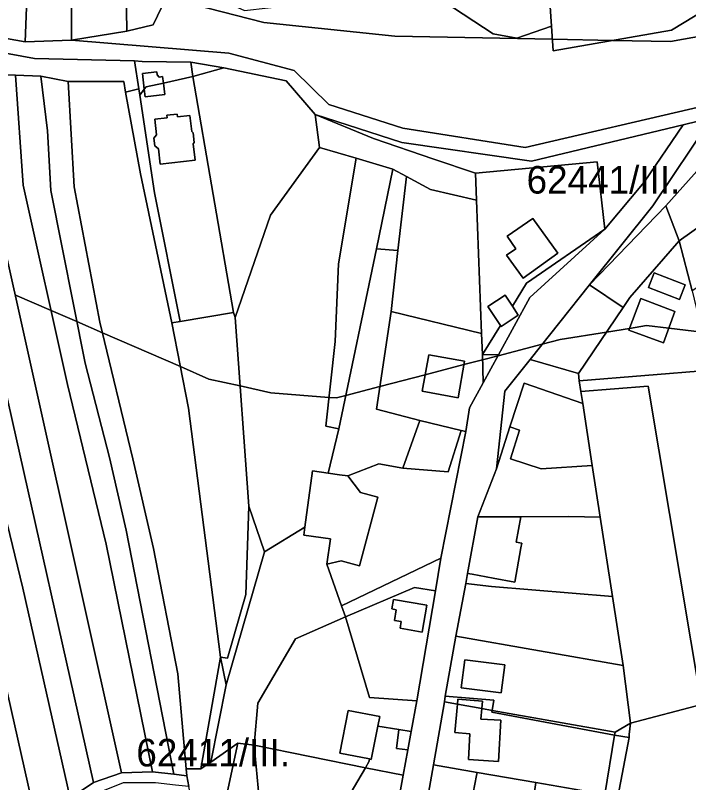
# Model space of a CAD drawing. Extents: x -502026 to -497664, y -1143484 to -1138019.
# Drawn here: x -499368.7 to -499173.2, y -1141026.2 to -1140803.4 of the extents above; entities that cross this region are included whole.
import ezdxf

# ---------------------------------------------------------------- set-up
doc = ezdxf.new("R2010")
doc.units = 0
for name, color, linetype in [('25', 7, 'Continuous'), ('37', 7, 'Continuous'), ('43', 7, 'Continuous'), ('49', 7, 'Continuous'), ('55', 7, 'Continuous'), ('62', 7, 'Continuous'), ('7', 7, 'Continuous')]:
    doc.layers.add(name, color=color, linetype=linetype)

msp = doc.modelspace()

# ---------------------------------------------------------------- linework, layer by layer
at = {"layer": '25'}
for points in [[(-499197.54, -1140865.53), (-499220.31, -1140881.21), (-499224.42, -1140887.86), (-499226.54, -1140884.64), (-499231.53, -1140887.94), (-499227.88, -1140893.47), (-499233.09, -1140901.89), (-499233.33, -1140895.75), (-499234.85, -1140857.1), (-499235.11, -1140849.28), (-499199.75, -1140845.95)], [(-499211.18, -1140872.5), (-499218.51, -1140862.37), (-499225.92, -1140867.49), (-499223.41, -1140871.18), (-499226.08, -1140873), (-499221.25, -1140879.73)], [(-499172.2, -1140883.42), (-499168.7, -1140897.93), (-499166.92, -1140906.4), (-499204.99, -1140909.49), (-499205.25, -1140907.4), (-499192.25, -1140888.2), (-499190.28, -1140885.29), (-499175.96, -1140868.88)], [(-499174.29, -1140881.66), (-499183.26, -1140878.2), (-499184.91, -1140882.42), (-499175.92, -1140885.89)], [(-499177.24, -1140889.37), (-499187.16, -1140885.61), (-499190.64, -1140894.79), (-499180.52, -1140898.45)], [(-499304.87, -1140891.11), (-499300.88, -1140945.93), (-499301.8, -1140971.52), (-499307.12, -1140990.05), (-499309.15, -1140989.78), (-499318.38, -1140917.5), (-499323.23, -1140892.73), (-499320.84, -1140892.29), (-499305.38, -1140889.66)], [(-499233.33, -1140895.75), (-499233.09, -1140901.89), (-499232.84, -1140910.06), (-499236.82, -1140917.34), (-499237.88, -1140924.28), (-499239.24, -1140923.94), (-499251.3, -1140921.01), (-499263.86, -1140917.78), (-499259.57, -1140889.43)], [(-499238.33, -1140903.78), (-499248.65, -1140901.96), (-499250.57, -1140912.55), (-499240.17, -1140914.47)], [(-499149.96, -1140998.01), (-499169.47, -1141003.49), (-499185.03, -1140911.08), (-499204.51, -1140912.61), (-499204.99, -1140909.49), (-499166.92, -1140906.4), (-499166.32, -1140909.62)], [(-499169.47, -1141003.49), (-499190.13, -1141008.87), (-499192.27, -1140992.2), (-499195.38, -1140972.18), (-499198.96, -1140949.07), (-499201.24, -1140934.07), (-499203.98, -1140916.08), (-499204.51, -1140912.61), (-499185.03, -1140911.08)], [(-499239.24, -1140923.94), (-499243.03, -1140935.97), (-499256.25, -1140934.9), (-499251.3, -1140921.01)], [(-499237.88, -1140924.28), (-499245.16, -1140961.04), (-499274.05, -1140974.83), (-499278.24, -1140962.75), (-499274.1, -1140961.77), (-499268.82, -1140963.21), (-499263.44, -1140943.34), (-499268.48, -1140941.98), (-499272.21, -1140937.1), (-499263.21, -1140933.63), (-499256.25, -1140934.9), (-499243.03, -1140935.97), (-499239.24, -1140923.94)], [(-499201.24, -1140934.07), (-499198.96, -1140949.07), (-499207.98, -1140948.89), (-499221.95, -1140948.97), (-499234.39, -1140949.05), (-499229.06, -1140935.09), (-499225.13, -1140922.92), (-499222.32, -1140923.81), (-499224.98, -1140932.15), (-499216.06, -1140935.06)], [(-499198.96, -1140949.07), (-499195.38, -1140972.18), (-499230.44, -1140969.23), (-499237.96, -1140968.39), (-499237.4, -1140965.44), (-499236.07, -1140965.69), (-499230, -1140966.78), (-499223.72, -1140967.95), (-499221.96, -1140958.01), (-499221.67, -1140956.64), (-499223.31, -1140956.33), (-499221.95, -1140948.97), (-499207.98, -1140948.89)], [(-499278.24, -1140962.75), (-499274.05, -1140974.83), (-499272.81, -1140978.04), (-499287.31, -1140984.39), (-499298.29, -1141003.14), (-499299.38, -1141015.27), (-499304.05, -1141014.72), (-499311.97, -1141020.25), (-499307.52, -1140997.79), (-499296.35, -1140959.15), (-499284.66, -1140951.98), (-499284.98, -1140954.32), (-499277.15, -1140955.39)], [(-499195.38, -1140972.18), (-499192.27, -1140992.2), (-499240.81, -1140983.63), (-499237.96, -1140968.39), (-499230.44, -1140969.23)], [(-499246.75, -1140970.51), (-499252.11, -1141002.41), (-499265.85, -1141001.45), (-499272.81, -1140978.04), (-499252.78, -1140969.56)], [(-499249.2, -1140974.61), (-499258.96, -1140972.98), (-499259.42, -1140975.76), (-499258.11, -1140975.98), (-499258.62, -1140979.06), (-499256.67, -1140979.38), (-499257, -1140981.35), (-499250.62, -1140982.5)], [(-499252.11, -1141002.41), (-499253.8, -1141011.37), (-499257.38, -1141010.76), (-499263.46, -1141009.82), (-499262.91, -1141007.02), (-499272.06, -1141005.24), (-499274.5, -1141017.6), (-499265.89, -1141019.3), (-499265.96, -1141019.96), (-499267.06, -1141021.83), (-499299.38, -1141015.27), (-499298.29, -1141003.14), (-499287.31, -1140984.39), (-499272.81, -1140978.04), (-499265.85, -1141001.45)], [(-499192.27, -1140992.2), (-499190.13, -1141008.87), (-499194.56, -1141011.49), (-499230.28, -1141005.19), (-499229.81, -1141002.27), (-499243.87, -1141001.08), (-499240.81, -1140983.63)], [(-499226.6, -1140991.99), (-499238.2, -1140990.48), (-499239.26, -1140998.61), (-499227.66, -1141000.12)], [(-499230.28, -1141005.19), (-499233.26, -1141004.68), (-499233.04, -1141002.55), (-499240.26, -1141001.93), (-499240.38, -1141003.42), (-499244.15, -1141002.76), (-499243.87, -1141001.08), (-499229.81, -1141002.27)], [(-499240.38, -1141003.42), (-499241.07, -1141011.66), (-499236.71, -1141011.96), (-499237.13, -1141019.48), (-499228.43, -1141020.02), (-499227.73, -1141008.05), (-499233.56, -1141007.73), (-499233.26, -1141004.68), (-499230.28, -1141005.19), (-499230.36, -1141005.73), (-499194.72, -1141012.36), (-499197.6, -1141029.59), (-499217.58, -1141026.14), (-499234.64, -1141023.19), (-499247.31, -1141021), (-499244.15, -1141002.76)], [(-499194.56, -1141011.49), (-499194.72, -1141012.36), (-499230.36, -1141005.73), (-499230.28, -1141005.19)], [(-499299.38, -1141015.27), (-499297.29, -1141036.96), (-499298.32, -1141041.92), (-499309.49, -1141040), (-499304.05, -1141014.72)], [(-499267.06, -1141021.83), (-499272.46, -1141031.03), (-499275.72, -1141040.45), (-499277.52, -1141045.65), (-499281.4, -1141044.73), (-499298.32, -1141041.92), (-499297.29, -1141036.96), (-499299.38, -1141015.27)], [(-499234.64, -1141023.19), (-499234.82, -1141024.1), (-499235.82, -1141029.13), (-499237.29, -1141028.84), (-499237.66, -1141030.69), (-499236.19, -1141030.98), (-499237.06, -1141035.33), (-499229.07, -1141036.96), (-499227.41, -1141037.3), (-499227.95, -1141041), (-499222.45, -1141041.81), (-499222.37, -1141041.27), (-499219.87, -1141041.64), (-499219.24, -1141037.37), (-499217.58, -1141026.14), (-499197.6, -1141029.59), (-499199.94, -1141043.6), (-499205.07, -1141047.08), (-499250.48, -1141039.11), (-499247.31, -1141021)]]:
    msp.add_lwpolyline(points, close=True, dxfattribs=at)
at = {"layer": '37'}
for points in [[(-499093.69, -1140800.62), (-499104.95, -1140814.88), (-499109.51, -1140803.7), (-499127.89, -1140814.52), (-499149.4, -1140825.3), (-499162.04, -1140835.16), (-499163.96, -1140837.47), (-499165.34, -1140840.32), (-499168.31, -1140844.22), (-499168.31, -1140845.8), (-499179.89, -1140858.73), (-499202.02, -1140881.64), (-499183.66, -1140858.73), (-499166.49, -1140833.21), (-499109.48, -1140803.35), (-499095.98, -1140796.53)], [(-499305.38, -1140889.66), (-499320.84, -1140892.29), (-499328.27, -1140854.9), (-499332.57, -1140826.63), (-499331.24, -1140824.89), (-499330.99, -1140827.12), (-499325.29, -1140826.38), (-499325.71, -1140823.08), (-499317.16, -1140821.14)], [(-499158.93, -1140856.74), (-499175.96, -1140868.88), (-499179.89, -1140858.73), (-499168.31, -1140845.8), (-499168.31, -1140844.22), (-499165.34, -1140840.32), (-499163.96, -1140837.47), (-499162.04, -1140835.16), (-499149.4, -1140825.3), (-499165.76, -1140843.54)], [(-499321.7, -1140832.11), (-499324.66, -1140832.44), (-499324.57, -1140833.15), (-499328.14, -1140833.59), (-499327.66, -1140838.07), (-499328.45, -1140839.09), (-499328.18, -1140841.33), (-499327.15, -1140842.16), (-499326.61, -1140846.63), (-499316.5, -1140845.46), (-499317.05, -1140840.74), (-499316.74, -1140840.29), (-499317.06, -1140837.57), (-499317.46, -1140837.14), (-499318.01, -1140832.46), (-499321.63, -1140832.86)], [(-499269.76, -1140844.9), (-499274.85, -1140875.52), (-499275.85, -1140898.11), (-499278.57, -1140922.64), (-499274.78, -1140923.45), (-499277.84, -1140936.32), (-499282.42, -1140935.7), (-499284.66, -1140951.98), (-499296.35, -1140959.15), (-499300.88, -1140945.93), (-499304.87, -1140891.11), (-499294.61, -1140861.42), (-499280.38, -1140841.77)], [(-499172.2, -1140883.42), (-499175.96, -1140868.88), (-499158.93, -1140856.74), (-499141.03, -1140844.02), (-499134.24, -1140858.85)], [(-499259.06, -1140848.12), (-499263.87, -1140871.19), (-499274.78, -1140923.45), (-499278.57, -1140922.64), (-499275.85, -1140898.11), (-499274.85, -1140875.52), (-499269.76, -1140844.9)], [(-499255.12, -1140850.19), (-499257.68, -1140871.65), (-499263.87, -1140871.19), (-499259.06, -1140848.12)], [(-499234.85, -1140857.1), (-499233.33, -1140895.75), (-499259.57, -1140889.43), (-499257.68, -1140871.65), (-499255.12, -1140850.19), (-499248.22, -1140854)], [(-499175.96, -1140868.88), (-499190.28, -1140885.29), (-499192.25, -1140888.2), (-499202.02, -1140881.64), (-499179.89, -1140858.73)], [(-499257.68, -1140871.65), (-499259.57, -1140889.43), (-499263.86, -1140917.78), (-499251.3, -1140921.01), (-499256.25, -1140934.9), (-499263.21, -1140933.63), (-499272.21, -1140937.1), (-499274.6, -1140936.77), (-499277.84, -1140936.32), (-499274.78, -1140923.45), (-499263.87, -1140871.19)], [(-499192.25, -1140888.2), (-499205.25, -1140907.4), (-499219.29, -1140903.33), (-499202.02, -1140881.64)], [(-499205.25, -1140907.4), (-499204.99, -1140909.49), (-499204.51, -1140912.61), (-499203.98, -1140916.08), (-499221.01, -1140910.17), (-499225.13, -1140922.92), (-499229.06, -1140935.09), (-499226.63, -1140912.54), (-499219.29, -1140903.33)], [(-499296.35, -1140959.15), (-499307.52, -1140997.79), (-499309.15, -1140989.78), (-499307.12, -1140990.05), (-499301.8, -1140971.52), (-499300.88, -1140945.93)], [(-499307.52, -1140997.79), (-499311.97, -1141020.25), (-499314.88, -1141022.19), (-499309.15, -1140989.78)], [(-499167.34, -1141225.18), (-499190.36, -1141233.78), (-499185.74, -1141195.87), (-499181.22, -1141101.09), (-499185.55, -1141045.62), (-499196.67, -1141045.66), (-499193.78, -1141030.25), (-499190.54, -1141013.08), (-499190.51, -1141012.2), (-499190.13, -1141008.87), (-499169.47, -1141003.49), (-499161.86, -1141074.87), (-499164.09, -1141140.88)], [(-499253.8, -1141011.37), (-499254.75, -1141016.63), (-499258.07, -1141016.22), (-499257.38, -1141010.76)]]:
    msp.add_lwpolyline(points, close=True, dxfattribs=at)
at = {"layer": '43'}
msp.add_lwpolyline([(-499098.45, -1140792.47), (-499169.08, -1140829.79), (-499220.72, -1140841.83), (-499256.21, -1140836.16), (-499277.72, -1140829.32), (-499287.7, -1140819.38), (-499306.66, -1140814.44), (-499352.42, -1140810.64), (-499336.3, -1140807.98), (-499328.65, -1140806.13), (-499324.82, -1140798.07), (-499318.22, -1140791.11), (-499315.45, -1140795.96), (-499302.12, -1140802.04), (-499267.8, -1140798.07), (-499244.32, -1140799.43), (-499230, -1140808.8), (-499223.13, -1140810.06), (-499213.06, -1140806.58), (-499212.54, -1140813.69), (-499178.21, -1140807.73), (-499161.8, -1140797.63), (-499134.65, -1140793.45), (-499107.41, -1140785.15)], close=True, dxfattribs=at)
at = {"layer": '49'}
for points in [[(-499213.58, -1140799.48), (-499213.06, -1140806.58), (-499223.13, -1140810.06), (-499230, -1140808.8), (-499244.32, -1140799.43)], [(-499161.8, -1140797.63), (-499178.21, -1140807.73), (-499212.54, -1140813.69), (-499213.06, -1140806.58), (-499213.58, -1140799.48)]]:
    msp.add_lwpolyline(points, dxfattribs=at)
at = {"layer": '55'}
for points in [[(-499411.74, -1140801.37), (-499390.44, -1140806.13), (-499384.16, -1140807.53), (-499376.79, -1140809.18), (-499365.81, -1140811.09), (-499352.42, -1140810.64), (-499306.66, -1140814.44), (-499287.7, -1140819.38), (-499277.72, -1140829.32), (-499256.21, -1140836.16), (-499220.72, -1140841.83), (-499169.08, -1140829.79), (-499098.45, -1140792.47)], [(-499109.48, -1140803.35), (-499166.49, -1140833.21), (-499174.8, -1140835.2), (-499218.89, -1140845.72), (-499256.52, -1140840.37), (-499281.61, -1140832.2), (-499290.1, -1140822.45), (-499308.12, -1140818.62), (-499317.73, -1140817), (-499331.83, -1140816.86), (-499334.13, -1140816.64), (-499363.08, -1140815.92), (-499412.53, -1140806.88), (-499433.39, -1140809.57), (-499443.61, -1140810.8), (-499451.13, -1140803.54), (-499477.19, -1140803.19), (-499501.07, -1140809.22), (-499520.46, -1140808.75), (-499530.45, -1140804.22), (-499532.5, -1140804.46), (-499550.63, -1140806.59)], [(-499258.3, -1141036.16), (-499256.1, -1141024.05), (-499254.75, -1141016.63), (-499253.8, -1141011.37), (-499252.11, -1141002.41), (-499246.75, -1140970.51), (-499245.16, -1140961.04), (-499237.88, -1140924.28), (-499236.82, -1140917.34), (-499232.84, -1140910.06), (-499228.39, -1140901.93), (-499219.31, -1140885.35), (-499197.54, -1140865.53), (-499186.16, -1140851.8), (-499174.8, -1140835.2), (-499166.49, -1140833.21), (-499183.66, -1140858.73), (-499202.02, -1140881.64), (-499219.29, -1140903.33), (-499226.63, -1140912.54), (-499229.06, -1140935.09), (-499234.39, -1140949.05), (-499237.4, -1140965.44), (-499237.96, -1140968.39), (-499240.81, -1140983.63), (-499243.87, -1141001.08), (-499244.15, -1141002.76), (-499247.31, -1141021), (-499250.48, -1141039.11)]]:
    msp.add_lwpolyline(points, dxfattribs=at)
for points in [[(-499334.13, -1140816.64), (-499332.86, -1140824.76), (-499336.66, -1140825.71), (-499337.23, -1140822.63), (-499353.36, -1140822.64), (-499361.27, -1140821.06), (-499368.62, -1140820.79), (-499378.44, -1140820.43), (-499389.02, -1140817.72), (-499400.07, -1140816.06), (-499411.8, -1140814.3), (-499423.03, -1140811.84), (-499433.39, -1140809.57), (-499412.53, -1140806.88), (-499363.08, -1140815.92)], [(-499317.73, -1140817), (-499317.16, -1140821.14), (-499325.71, -1140823.08), (-499325.96, -1140821.17), (-499326.97, -1140821.32), (-499327.5, -1140820.64), (-499327.63, -1140819.79), (-499331.74, -1140820.34), (-499331.24, -1140824.89), (-499332.57, -1140826.63), (-499332.86, -1140824.76), (-499334.13, -1140816.64), (-499331.83, -1140816.86)], [(-499308.12, -1140818.62), (-499317.16, -1140821.14), (-499317.73, -1140817)], [(-499325.71, -1140823.08), (-499330.71, -1140824.21), (-499331.24, -1140824.89), (-499331.74, -1140820.34), (-499327.63, -1140819.79), (-499327.5, -1140820.64), (-499326.97, -1140821.32), (-499325.96, -1140821.17)], [(-499331.24, -1140824.89), (-499330.71, -1140824.21), (-499325.71, -1140823.08), (-499325.29, -1140826.38), (-499330.99, -1140827.12)], [(-499332.57, -1140826.63), (-499328.27, -1140854.9), (-499320.84, -1140892.29), (-499323.23, -1140892.73), (-499332.37, -1140849.39), (-499336.66, -1140825.71), (-499332.86, -1140824.76)], [(-499321.7, -1140832.11), (-499321.63, -1140832.86), (-499318.01, -1140832.46), (-499317.46, -1140837.14), (-499317.06, -1140837.57), (-499316.74, -1140840.29), (-499317.05, -1140840.74), (-499316.5, -1140845.46), (-499326.61, -1140846.63), (-499327.15, -1140842.16), (-499328.18, -1140841.33), (-499328.45, -1140839.09), (-499327.66, -1140838.07), (-499328.14, -1140833.59), (-499324.57, -1140833.15), (-499324.66, -1140832.44)], [(-499235.11, -1140849.28), (-499234.85, -1140857.1), (-499248.22, -1140854), (-499255.12, -1140850.19), (-499259.06, -1140848.12), (-499269.76, -1140844.9), (-499280.38, -1140841.77), (-499281.61, -1140832.2), (-499264.76, -1140839.14), (-499247.22, -1140845.16)], [(-499174.8, -1140835.2), (-499186.16, -1140851.8), (-499197.54, -1140865.53), (-499199.75, -1140845.95), (-499235.11, -1140849.28), (-499247.22, -1140845.16), (-499264.76, -1140839.14), (-499281.61, -1140832.2), (-499256.52, -1140840.37), (-499218.89, -1140845.72)], [(-499211.18, -1140872.5), (-499221.25, -1140879.73), (-499226.08, -1140873), (-499223.41, -1140871.18), (-499225.92, -1140867.49), (-499218.51, -1140862.37)], [(-499228.39, -1140901.93), (-499233.09, -1140901.89), (-499227.88, -1140893.47), (-499227.67, -1140893.79), (-499222.69, -1140890.48), (-499224.42, -1140887.86), (-499220.31, -1140881.21), (-499197.54, -1140865.53), (-499219.31, -1140885.35)], [(-499174.29, -1140881.66), (-499175.92, -1140885.89), (-499184.91, -1140882.42), (-499183.26, -1140878.2)], [(-499224.42, -1140887.86), (-499222.69, -1140890.48), (-499227.67, -1140893.79), (-499227.88, -1140893.47), (-499231.53, -1140887.94), (-499226.54, -1140884.64)], [(-499177.24, -1140889.37), (-499180.52, -1140898.45), (-499190.64, -1140894.79), (-499187.16, -1140885.61)], [(-499238.33, -1140903.78), (-499240.17, -1140914.47), (-499250.57, -1140912.55), (-499248.65, -1140901.96)], [(-499228.39, -1140901.93), (-499232.84, -1140910.06), (-499233.09, -1140901.89)], [(-499203.98, -1140916.08), (-499201.24, -1140934.07), (-499216.06, -1140935.06), (-499224.98, -1140932.15), (-499222.32, -1140923.81), (-499225.13, -1140922.92), (-499221.01, -1140910.17)], [(-499277.84, -1140936.32), (-499274.6, -1140936.77), (-499272.21, -1140937.1), (-499268.48, -1140941.98), (-499263.44, -1140943.34), (-499268.82, -1140963.21), (-499274.1, -1140961.77), (-499278.24, -1140962.75), (-499277.15, -1140955.39), (-499284.98, -1140954.32), (-499284.66, -1140951.98), (-499282.42, -1140935.7)], [(-499237.4, -1140965.44), (-499234.39, -1140949.05), (-499221.95, -1140948.97), (-499223.31, -1140956.33), (-499221.67, -1140956.64), (-499221.96, -1140958.01), (-499223.72, -1140967.95), (-499230, -1140966.78), (-499236.07, -1140965.69)], [(-499246.75, -1140970.51), (-499252.78, -1140969.56), (-499272.81, -1140978.04), (-499274.05, -1140974.83), (-499245.16, -1140961.04)], [(-499249.2, -1140974.61), (-499250.62, -1140982.5), (-499257, -1140981.35), (-499256.67, -1140979.38), (-499258.62, -1140979.06), (-499258.11, -1140975.98), (-499259.42, -1140975.76), (-499258.96, -1140972.98)], [(-499226.6, -1140991.99), (-499227.66, -1141000.12), (-499239.26, -1140998.61), (-499238.2, -1140990.48)], [(-499233.26, -1141004.68), (-499240.38, -1141003.42), (-499240.26, -1141001.93), (-499233.04, -1141002.55)], [(-499233.26, -1141004.68), (-499233.56, -1141007.73), (-499227.73, -1141008.05), (-499228.43, -1141020.02), (-499237.13, -1141019.48), (-499236.71, -1141011.96), (-499241.07, -1141011.66), (-499240.38, -1141003.42)], [(-499263.46, -1141009.82), (-499265.35, -1141019.41), (-499265.89, -1141019.3), (-499274.5, -1141017.6), (-499272.06, -1141005.24), (-499262.91, -1141007.02)], [(-499190.54, -1141013.08), (-499194.72, -1141012.36), (-499194.56, -1141011.49), (-499190.13, -1141008.87), (-499190.51, -1141012.2)], [(-499257.38, -1141010.76), (-499258.07, -1141016.22), (-499254.75, -1141016.63), (-499256.1, -1141024.05), (-499267.06, -1141021.83), (-499265.96, -1141019.96), (-499265.89, -1141019.3), (-499265.35, -1141019.41), (-499263.46, -1141009.82)], [(-499190.54, -1141013.08), (-499193.78, -1141030.25), (-499197.6, -1141029.59), (-499194.72, -1141012.36)], [(-499309.49, -1141040), (-499316.03, -1141038.88), (-499318.32, -1141027.25), (-499318.92, -1141024.22), (-499319.1, -1141022.16), (-499314.88, -1141022.19), (-499311.97, -1141020.25), (-499304.05, -1141014.72)], [(-499256.1, -1141024.05), (-499258.3, -1141036.16), (-499260.74, -1141049.54), (-499263.59, -1141048.97), (-499262.19, -1141045.13), (-499275.72, -1141040.45), (-499272.46, -1141031.03), (-499267.06, -1141021.83)], [(-499217.58, -1141026.14), (-499219.24, -1141037.37), (-499219.87, -1141041.64), (-499222.37, -1141041.27), (-499222.45, -1141041.81), (-499227.95, -1141041), (-499227.41, -1141037.3), (-499229.07, -1141036.96), (-499237.06, -1141035.33), (-499236.19, -1141030.98), (-499237.66, -1141030.69), (-499237.29, -1141028.84), (-499235.82, -1141029.13), (-499234.82, -1141024.1), (-499234.64, -1141023.19)]]:
    msp.add_lwpolyline(points, close=True, dxfattribs=at)
at = {"layer": '62'}
for points in [[(-499324.86, -1140798.16), (-499296.5, -1140805.5), (-499258.5, -1140809.5), (-499212.78, -1140810.36), (-499195.24, -1140810.69), (-499178.5, -1140811), (-499131, -1140802.5)], [(-499131, -1140802.5), (-499178.5, -1140811), (-499195.24, -1140810.69), (-499212.78, -1140810.36), (-499258.5, -1140809.5), (-499296.5, -1140805.5), (-499324.86, -1140798.16)], [(-499368.82, -1140884.51), (-499358.32, -1140889.08), (-499350.82, -1140892.34), (-499343.41, -1140895.56), (-499320.75, -1140905.41), (-499312.5, -1140909), (-499303.42, -1140911.02), (-499294.5, -1140913), (-499277.65, -1140914.33), (-499275.5, -1140914.5), (-499272.76, -1140913.78), (-499262.86, -1140911.19), (-499249.7, -1140907.75), (-499238.51, -1140904.82), (-499235.79, -1140904.11), (-499233.04, -1140903.4), (-499228.55, -1140902.22), (-499215.74, -1140898.87), (-499210.5, -1140897.5), (-499197.09, -1140895.35), (-499190.45, -1140894.29), (-499185.5, -1140893.5), (-499179, -1140894.24), (-499169.32, -1140895.35)], [(-499169.32, -1140895.35), (-499179, -1140894.24), (-499185.5, -1140893.5), (-499190.45, -1140894.29), (-499197.09, -1140895.35), (-499210.5, -1140897.5), (-499215.74, -1140898.87), (-499228.55, -1140902.22), (-499233.04, -1140903.4), (-499235.79, -1140904.11), (-499238.51, -1140904.82), (-499249.7, -1140907.75), (-499262.86, -1140911.19), (-499272.76, -1140913.78), (-499275.5, -1140914.5), (-499277.65, -1140914.33), (-499294.5, -1140913), (-499303.42, -1140911.02), (-499312.5, -1140909), (-499320.75, -1140905.41), (-499343.41, -1140895.56), (-499350.82, -1140892.34), (-499358.32, -1140889.08), (-499368.82, -1140884.51)]]:
    msp.add_lwpolyline(points, dxfattribs=at)
at = {"layer": '7'}
for points in [[(-499361.92, -1140659.52), (-499362.02, -1140713.37), (-499365.81, -1140811.09), (-499376.79, -1140809.18), (-499375.03, -1140655.39), (-499368.85, -1140652.22)], [(-499348.98, -1140662.77), (-499352.78, -1140723.14), (-499352.42, -1140810.64), (-499365.81, -1140811.09), (-499362.02, -1140713.37), (-499361.92, -1140659.52)], [(-499325.18, -1140666.98), (-499326.25, -1140697.39), (-499326.78, -1140757.9), (-499324.82, -1140798.07), (-499328.65, -1140806.13), (-499336.3, -1140807.98), (-499337.73, -1140716.01), (-499336.17, -1140665.33), (-499330.61, -1140666.33), (-499333.87, -1140661.11)], [(-499336.17, -1140665.33), (-499337.73, -1140716.01), (-499336.3, -1140807.98), (-499352.42, -1140810.64), (-499352.78, -1140723.14), (-499348.98, -1140662.77)], [(-499411.8, -1140814.3), (-499401.41, -1140870.3), (-499388.23, -1140923.56), (-499362.13, -1141039.35), (-499370.89, -1141048.08), (-499389.64, -1140960.66), (-499402.56, -1140906.21), (-499413.83, -1140861.17), (-499423.03, -1140811.84)], [(-499400.07, -1140816.06), (-499390.92, -1140869.47), (-499366.47, -1140969.75), (-499352.75, -1141030.64), (-499362.13, -1141039.35), (-499388.23, -1140923.56), (-499401.41, -1140870.3), (-499411.8, -1140814.3)], [(-499389.02, -1140817.72), (-499385.41, -1140850.57), (-499378.38, -1140886.85), (-499371.85, -1140910.98), (-499346.02, -1141026.16), (-499352.75, -1141030.64), (-499366.47, -1140969.75), (-499390.92, -1140869.47), (-499400.07, -1140816.06)], [(-499378.44, -1140820.43), (-499375.21, -1140855.85), (-499337.86, -1141023.34), (-499346.02, -1141026.16), (-499371.85, -1140910.98), (-499378.38, -1140886.85), (-499385.41, -1140850.57), (-499389.02, -1140817.72)], [(-499281.61, -1140832.2), (-499280.38, -1140841.77), (-499294.61, -1140861.42), (-499304.87, -1140891.11), (-499305.38, -1140889.66), (-499317.16, -1140821.14), (-499308.12, -1140818.62), (-499290.1, -1140822.45)], [(-499368.62, -1140820.79), (-499366.41, -1140852.67), (-499353.55, -1140910.55), (-499342.28, -1140956.97), (-499328.85, -1141023.08), (-499337.86, -1141023.34), (-499375.21, -1140855.85), (-499378.44, -1140820.43)], [(-499361.27, -1140821.06), (-499359.31, -1140836.99), (-499358.37, -1140854.26), (-499348.43, -1140904.4), (-499341.39, -1140931.75), (-499336.52, -1140952.88), (-499322.67, -1141023.72), (-499328.85, -1141023.08), (-499342.28, -1140956.97), (-499353.55, -1140910.55), (-499366.41, -1140852.67), (-499368.62, -1140820.79)], [(-499353.36, -1140822.64), (-499351.63, -1140853.18), (-499344.15, -1140892.49), (-499334.6, -1140932.18), (-499328.61, -1140958.21), (-499321.5, -1140994.55), (-499319.1, -1141022.16), (-499318.92, -1141024.22), (-499322.67, -1141023.72), (-499336.52, -1140952.88), (-499341.39, -1140931.75), (-499348.43, -1140904.4), (-499358.37, -1140854.26), (-499359.31, -1140836.99), (-499361.27, -1140821.06)], [(-499336.66, -1140825.71), (-499332.37, -1140849.39), (-499323.23, -1140892.73), (-499318.38, -1140917.5), (-499309.15, -1140989.78), (-499314.88, -1141022.19), (-499319.1, -1141022.16), (-499321.5, -1140994.55), (-499328.61, -1140958.21), (-499334.6, -1140932.18), (-499344.15, -1140892.49), (-499351.63, -1140853.18), (-499353.36, -1140822.64), (-499337.23, -1140822.63)]]:
    msp.add_lwpolyline(points, close=True, dxfattribs=at)
msp.add_lwpolyline([(-499370.89, -1141048.08), (-499362.13, -1141039.35), (-499352.75, -1141030.64), (-499346.02, -1141026.16), (-499337.86, -1141023.34), (-499328.85, -1141023.08), (-499322.67, -1141023.72), (-499318.92, -1141024.22), (-499318.32, -1141027.25), (-499322.17, -1141026.88), (-499328.01, -1141026.2), (-499337.35, -1141026.2), (-499345.35, -1141029.43), (-499352.29, -1141034.82), (-499362.67, -1141044.51), (-499371.13, -1141051.99)], dxfattribs=at)

# ---------------------------------------------------------------- texts
at = {"layer": '62'}
for s, p in [('62441/III.', (-499220.28, -1140855.16)), ('62411/III.', (-499333.55, -1141021.47))]:
    msp.add_text(s, height=8, dxfattribs=at).set_placement(p)

doc.saveas('drawing.dxf')
